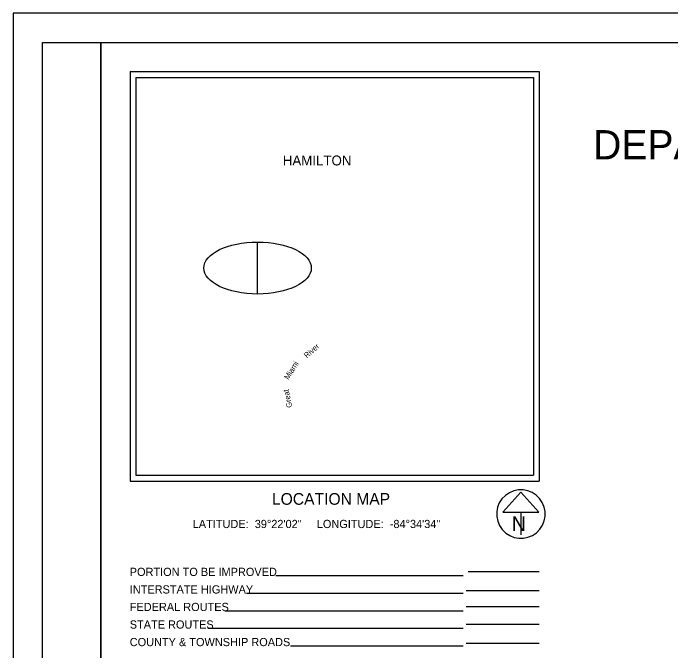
# Model space of a CAD drawing. Extents: x 0 to 45, y -99 to 22.
# Drawn here: x 0 to 11.25, y 11.1 to 22 of the extents above; entities that cross this region are included whole.
import ezdxf

# ---------------------------------------------------------------- set-up
doc = ezdxf.new("R2010")
doc.units = 0
for name, color, linetype in [('Default', 7, 'Continuous'), ('GM_X_Section', 7, 'Continuous'), ('SH_Border', 7, 'Continuous'), ('SH_Cut_Line', 7, 'Continuous'), ('SH_Data', 7, 'Continuous'), ('SH_Masking', 7, 'Continuous'), ('SH_Text', 7, 'Continuous')]:
    doc.layers.add(name, color=color, linetype=linetype)

msp = doc.modelspace()

# ---------------------------------------------------------------- linework, layer by layer
at = {"layer": 'GM_X_Section'}
msp.add_ellipse((4.181, 17.642), major_axis=(-0.919, 0), ratio=0.483696, dxfattribs=at)
at = {"layer": 'SH_Border'}
for points in [[(0.5, 21.5), (1.5, 21.5), (1.5, 0.5), (0.5, 0.5)], [(1.5, 21.5), (33.5, 21.5), (33.5, 0.5), (1.5, 0.5)]]:
    msp.add_lwpolyline(points, close=True, dxfattribs=at)
at = {"layer": 'SH_Cut_Line'}
for p, q in [((2, 21), (9, 21)), ((2, 21), (2, 14)), ((9, 21), (9, 14)), ((2.1, 20.9), (2.1, 14.1)), ((2.1, 20.9), (8.9, 20.9)), ((8.9, 20.9), (8.9, 14.1)), ((2.1, 14.1), (8.9, 14.1)), ((2.1, 14.1), (2.1, 14.1)), ((2, 14), (9, 14)), ((8.685, 13.809), (8.377, 13.468)), ((8.992, 13.468), (8.685, 13.809)), ((8.377, 13.468), (8.992, 13.468)), ((8.685, 13.468), (8.685, 13.081)), ((8.685, 13.435), (8.685, 13.435)), ((8.685, 13.435), (8.685, 13.435)), ((7.7, 12.377), (4.494, 12.377)), ((7.783, 12.455), (9, 12.455)), ((7.7, 12.077), (3.99, 12.077)), ((9, 12.121), (7.75, 12.121)), ((9, 11.849), (7.75, 11.849)), ((7.7, 11.777), (3.619, 11.777)), ((7.7, 11.477), (3.329, 11.477)), ((9, 11.549), (7.75, 11.549)), ((7.7, 11.177), (4.745, 11.177)), ((9, 11.222), (7.75, 11.222))]:
    msp.add_line(p, q, dxfattribs=at)
msp.add_arc((8.685, 13.435), 0.415, 129.7798, 129.7633, dxfattribs=at)
at = {"layer": 'SH_Data'}
msp.add_lwpolyline([(0, 0), (34, 0), (34, 22), (0, 22)], close=True, dxfattribs=at)
at = {"layer": 'SH_Masking'}
msp.add_line((4.181, 17.198), (4.181, 18.087), dxfattribs=at)

# ---------------------------------------------------------------- texts
at = {"layer": 'Default'}
for s, height, rotation, p in [('HAMILTON', 0.17, 0, (4.612, 19.396)), ('River', 0.0947, 40.9046, (5.024, 16.095)), ('Miami', 0.0947, 57.577, (4.708, 15.725)), ('Great', 0.0947, 101.808, (4.775, 15.264))]:
    msp.add_text(s, height=height, rotation=rotation, dxfattribs=at).set_placement(p)
at = {"layer": 'SH_Cut_Line'}
msp.add_text('N', height=0.25, dxfattribs=at).set_placement((8.529, 13.144))
at = {"layer": 'SH_Text'}
for s, height, p in [('DEPARTMENT OF TRANSPORTATION', 0.5, (9.92, 19.5)), ('LOCATION MAP', 0.2, (4.427, 13.594)), ('LATITUDE:  39°22\'02"     LONGITUDE:  -84°34\'34"', 0.14, (3.071, 13.196)), ('PORTION TO BE IMPROVED', 0.14, (1.994, 12.377)), ('INTERSTATE HIGHWAY', 0.14, (1.994, 12.077)), ('FEDERAL ROUTES', 0.14, (1.994, 11.777)), ('STATE ROUTES', 0.14, (1.994, 11.477)), ('COUNTY & TOWNSHIP ROADS', 0.14, (1.994, 11.177))]:
    msp.add_text(s, height=height, dxfattribs=at).set_placement(p)

doc.saveas('drawing.dxf')
